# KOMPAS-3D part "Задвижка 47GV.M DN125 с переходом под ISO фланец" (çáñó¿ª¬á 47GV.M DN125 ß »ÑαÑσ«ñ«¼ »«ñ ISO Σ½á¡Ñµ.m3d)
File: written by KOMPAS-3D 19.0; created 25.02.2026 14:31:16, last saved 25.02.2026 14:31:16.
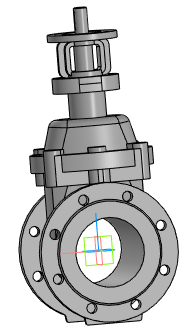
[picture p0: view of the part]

Document properties: Автор: Энергия; Полное имя файла: ..\..\47GVM\DR.47GVM.125.16.00.000\DR.47GVM.125.16.00.00 - Задвижка с обрезиненным клином DN125.a3d

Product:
- Part/product: Задвижка 47GV.M DN125 с переходом под ISO фланец
    Масса: 39.7563
  - Component: Задвижка с обрезиненным клином DN125. Сборочный чертеж  | designation DR.47GVM.125.16.00.00СБ  | pos. 0  | Масса: 25.3494; Раздел спецификации: Документация; Форматы листов документа: 2xA3; source file: 47GV.M DN125\DR.47GVM.125.16.00.000 СБ - Задвижка с обрезиненным клином DN125.cdw

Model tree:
1. Операция без истории:1

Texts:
  Точка начала. Х
  Точка начала. Y
  Точка начала. Z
